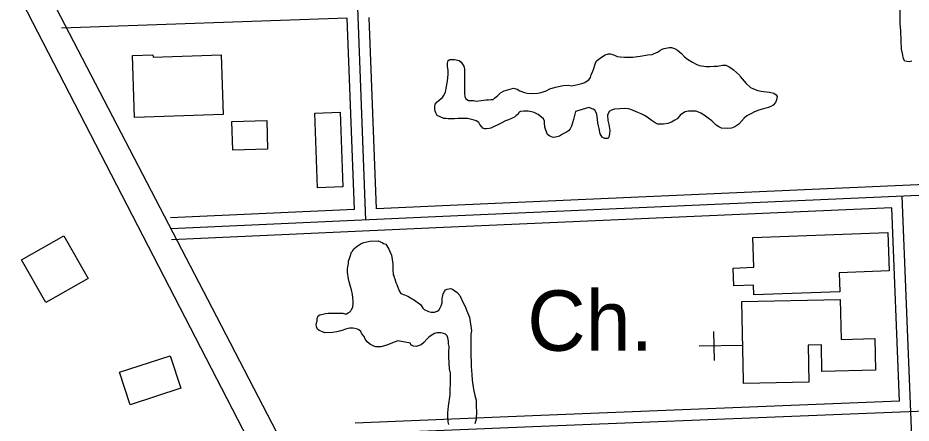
# Model space of a CAD drawing. Extents: x 3313442 to 3351311, y 721974 to 747360.
# Drawn here: x 3328908 to 3330135, y 735140 to 735697 of the extents above; entities that cross this region are included whole.
import ezdxf

# ---------------------------------------------------------------- set-up
doc = ezdxf.new("R2010")
doc.units = 0
for name, color, linetype in [('V-BLDG-OTLN', 7, 'Continuous'), ('V-ROAD-CNTR', 7, 'Continuous'), ('V-SITE-OTLN', 7, 'Continuous'), ('V-SITE-OTLN-IDEN', 7, 'Continuous'), ('V-SITE-VEGE', 7, 'Continuous')]:
    doc.layers.add(name, color=color, linetype=linetype)

msp = doc.modelspace()

# ---------------------------------------------------------------- linework, layer by layer
at = {"layer": 'V-BLDG-OTLN'}
for points in [[(3329067.9, 735559.9), (3329065.1, 735645.1), (3329093.4, 735646), (3329093.5, 735642.7), (3329187.1, 735645.9), (3329189.9, 735564)], [(3329319.6, 735463.2), (3329315.7, 735565.8), (3329350.4, 735567.2), (3329354.3, 735464.5)], [(3329203, 735515.1), (3329201.8, 735554.5), (3329249.7, 735555.9), (3329250.9, 735516.5)], [(3328913, 735364.2), (3328971.1, 735397.3), (3329004.5, 735338.4), (3328946.4, 735305.4)], [(3329917.4, 735394.7), (3330102.7, 735401.6), (3330104.6, 735348.9), (3330035.9, 735346.4), (3330036.9, 735320.3), (3329918.9, 735315.9), (3329918.4, 735329.5), (3329891.3, 735328.5), (3329890.4, 735352.8), (3329918.9, 735353.9)], [(3329904.6, 735198.3), (3329902.3, 735306.9), (3330037.4, 735309.7), (3330038.5, 735254.9), (3330084.9, 735255.9), (3330085.8, 735212.4), (3330012.3, 735210.9), (3330011.5, 735247.3), (3329993.2, 735246.9), (3329994.3, 735195.9), (3329904.7, 735194)], [(3329047.6, 735209.9), (3329117.1, 735232.4), (3329131.6, 735187.6), (3329062.1, 735165.1)]]:
    msp.add_lwpolyline(points, close=True, dxfattribs=at)
at = {"layer": 'V-ROAD-CNTR'}
for points in [[(3329385.8, 735418.9), (3329331.6, 736855.2)], [(3328760.8, 736081.2), (3328936.7, 735756.3), (3329174.1, 735298.9), (3331685.5, 730453.7)], [(3328913.4, 735719.2), (3329483.8, 734613.6), (3331153.1, 731395.2)], [(3329360.3, 735696.3), (3328967.6, 735682.7)], [(3329370.2, 735433.2), (3329360.3, 735696.3)], [(3329400.2, 735434.5), (3329390.3, 735697.3)], [(3332480.2, 735555.8), (3329491.7, 735423.6), (3329118, 735406.9)], [(3330993.8, 735505), (3329491.1, 735438.6), (3329400.2, 735434.5)], [(3330146.4, 734858.1), (3330122.5, 735451.5)], [(3329370.2, 735433.2), (3329117.4, 735421.9)], [(3330108.2, 735435.8), (3329492.4, 735408.6), (3329118.7, 735391.9)], [(3330118.9, 735169.7), (3330108.2, 735435.8)], [(3332772.9, 735263.5), (3332071.4, 735231), (3330946.1, 735187.6), (3329615.1, 735134.6), (3329371.6, 735124.7)], [(3330118.9, 735169.7), (3329614.5, 735149.6), (3329371, 735139.7)]]:
    msp.add_lwpolyline(points, dxfattribs=at)
at = {"layer": 'V-SITE-OTLN'}
for p, q in [((3329863.2, 735265.7), (3329864, 735225.7)), ((3329903.6, 735246.5), (3329843.6, 735245.3))]:
    msp.add_line(p, q, dxfattribs=at)
at = {"layer": 'V-SITE-VEGE'}
for points in [[(3330135.6, 735637.5), (3330132.2, 735636.4), (3330126.3, 735637.4), (3330124.5, 735640.5), (3330122.8, 735647.7), (3330121.7, 735653.6), (3330120.9, 735665.7), (3330120.8, 735678.4), (3330120.1, 735684.3), (3330119.7, 735688.7), (3330119.6, 735700.4), (3330119.9, 735709.1), (3330119.8, 735715.3), (3330120.4, 735724.6), (3330120.4, 735730.1), (3330121, 735736.3), (3330121, 735739.4), (3330122, 735743.2), (3330122.7, 735745.3), (3330127.8, 735750.1), (3330131.9, 735753.6), (3330138.1, 735758.1)], [(3329700.1, 735631.9), (3329701.1, 735634.7), (3329702.8, 735637.8), (3329711, 735643.7), (3329714.4, 735645.8), (3329718.9, 735647.3), (3329721.3, 735647.3), (3329724.4, 735646.3), (3329727.2, 735645.6), (3329731, 735643.6), (3329735.1, 735643.3), (3329741, 735642.6), (3329752.7, 735642.7), (3329758.9, 735643.8), (3329762.7, 735644.2), (3329773, 735646), (3329778.9, 735646.4), (3329780.9, 735647.4), (3329787.1, 735650.2), (3329789.5, 735652), (3329792.9, 735653.7), (3329795.7, 735654.8), (3329802.6, 735655.9), (3329805.7, 735655.9), (3329809.8, 735654.5), (3329814, 735652.2), (3329819.2, 735647.7), (3329823.7, 735643.3), (3329827.5, 735639.9), (3329834.4, 735635.8), (3329839.3, 735633.1)], [(3329638.5, 735534.3), (3329635.4, 735536.7), (3329632.9, 735542.5), (3329631.8, 735546.6), (3329631.4, 735552.5), (3329631.1, 735554.9), (3329630, 735558), (3329622.7, 735563.8), (3329617.2, 735566.5), (3329613.4, 735567.5), (3329608.6, 735568.5), (3329603, 735568.4), (3329598.2, 735568.1), (3329596.2, 735567), (3329594.5, 735563.9), (3329592.4, 735562.5), (3329590, 735560.4), (3329581.8, 735556.6), (3329577.7, 735555.1), (3329571.8, 735552), (3329557.4, 735545.3), (3329555, 735544.6), (3329551.6, 735544.3), (3329549.1, 735544.2), (3329546.7, 735545.2), (3329545.3, 735547), (3329542.2, 735550.4), (3329540.8, 735552.8), (3329537.3, 735555.2), (3329534.6, 735556.2), (3329525.2, 735558.5), (3329512.8, 735558.4), (3329507.7, 735558), (3329498.7, 735558), (3329496, 735558.3), (3329492.9, 735558.3), (3329483.9, 735562.7), (3329481.8, 735566.1), (3329481.1, 735568.5), (3329480.7, 735571.9), (3329480.7, 735574.4), (3329481, 735578.1), (3329483.7, 735581.6), (3329489.2, 735586.1), (3329491.2, 735587.5), (3329492.6, 735589.6), (3329495, 735594.5), (3329496, 735600.3), (3329498, 735609.6), (3329498.3, 735614.8), (3329498.9, 735619), (3329498.9, 735624.5), (3329498.1, 735630.3), (3329497.8, 735634.5), (3329498.8, 735638.2), (3329501.2, 735639.6), (3329507.4, 735639.7), (3329513.9, 735638), (3329516.7, 735636), (3329520.5, 735630.2), (3329521.3, 735626.4), (3329521.5, 735592.6), (3329521.9, 735588.8), (3329523.3, 735585.7), (3329526.8, 735583.3), (3329529.9, 735583), (3329533.7, 735583), (3329537.5, 735582.4), (3329547.4, 735583.5), (3329551.2, 735584.2), (3329554.3, 735584.2), (3329557.4, 735584.6), (3329560.5, 735584.6), (3329562.9, 735586.7), (3329566.7, 735589.5), (3329570.8, 735593.7), (3329575.6, 735596.5), (3329588.7, 735600), (3329593.5, 735599), (3329597.3, 735596.7), (3329603.9, 735594.3), (3329607.3, 735593.3), (3329613.5, 735593), (3329621.8, 735593.1), (3329626.6, 735594.1), (3329633.5, 735596.6), (3329638.3, 735599.1), (3329646.5, 735601.5), (3329656.9, 735604), (3329663.8, 735604.1), (3329668.6, 735603.4), (3329676.8, 735605.2), (3329682.3, 735606.6), (3329686.5, 735608.1), (3329689.9, 735610.2), (3329692, 735611.5), (3329694.3, 735615), (3329695.3, 735618.5), (3329697.7, 735623.7), (3329699.1, 735627.1), (3329700.1, 735631.9)], [(3329839.3, 735633.1), (3329843.8, 735631.4), (3329853.4, 735630.1), (3329857.9, 735630.1), (3329864.1, 735630.2), (3329868.6, 735630.5), (3329875.8, 735631.6), (3329880.3, 735631.7), (3329884.8, 735629.6), (3329887.2, 735628.3), (3329891, 735625.2), (3329899, 735618), (3329900.1, 735616.3), (3329908.4, 735606.4), (3329914.3, 735601.3), (3329918.1, 735599.2), (3329924, 735596.9), (3329928.8, 735595.9), (3329936.1, 735594.9), (3329940.2, 735594.6), (3329946.4, 735593.3), (3329949.2, 735591.2), (3329950.9, 735588.5), (3329949.9, 735584.3), (3329948.6, 735580.5), (3329945.2, 735576.7), (3329942.1, 735575), (3329938.3, 735573.6), (3329925.6, 735569.7), (3329919.4, 735567.5), (3329915.6, 735565.4), (3329909.1, 735562.3), (3329905.3, 735558.8), (3329898.2, 735550.8), (3329892.7, 735547), (3329887.9, 735545.2), (3329882.4, 735544.8), (3329874.1, 735545.1), (3329870.6, 735546.8), (3329866.8, 735549.5), (3329860.9, 735555.4), (3329856.1, 735559.1), (3329850.5, 735563.2), (3329845.7, 735565.6), (3329841.9, 735567.6), (3329839.4, 735568.6), (3329828.8, 735568.5), (3329824.3, 735567.5), (3329820.9, 735565.4), (3329817.4, 735562.9), (3329816.1, 735561.2), (3329813.3, 735558.1), (3329810.3, 735556), (3329805.5, 735553.2), (3329800.6, 735551.8), (3329794.8, 735550.7), (3329786.9, 735550.6), (3329783.1, 735552.7), (3329777.5, 735556.4), (3329772.3, 735560.2), (3329768.5, 735562.5), (3329764, 735564.9), (3329759.5, 735566.9), (3329749.8, 735570.7), (3329746.7, 735571.7), (3329740.5, 735572), (3329734.7, 735571.9), (3329727.4, 735571.2), (3329723.3, 735570.1), (3329720.2, 735568), (3329717.8, 735563.2), (3329718.2, 735555.9), (3329719.7, 735550.4), (3329720.8, 735541.8), (3329720.5, 735537.3), (3329719.5, 735532.8), (3329718.4, 735531.1), (3329714, 735531.1), (3329710.5, 735532.8), (3329707.7, 735537.2), (3329707, 735539.6), (3329706.3, 735544.5), (3329705.2, 735548.6), (3329704.5, 735552.7), (3329704.1, 735557.5), (3329703, 735564.1), (3329702, 735566.5), (3329700.2, 735569.9), (3329698.1, 735571.3), (3329691.9, 735573.6), (3329673.7, 735568), (3329671, 735556.9), (3329668.3, 735547.9), (3329666.6, 735544.1), (3329664.3, 735541.7), (3329661.2, 735539.6), (3329656, 735536.8), (3329651.9, 735534.4), (3329646.1, 735532.6), (3329643, 735532.2), (3329638.5, 735534.3)], [(3329318.7, 735280.5), (3329319, 735283.6), (3329320.3, 735287), (3329322.7, 735288.8), (3329330.6, 735290.6), (3329334.1, 735290.9), (3329347.5, 735291), (3329354.1, 735290.8), (3329356.8, 735290.1), (3329359.2, 735290.1), (3329361.6, 735291.2), (3329363.4, 735292.2), (3329365.1, 735293.9), (3329366.1, 735296), (3329368.1, 735299.1), (3329368.4, 735304), (3329368.4, 735306.7), (3329368, 735312.6), (3329367.3, 735316.4), (3329365.9, 735322.9), (3329364.5, 735327.4), (3329363, 735333.9), (3329362, 735338), (3329360.8, 735347.3), (3329360.8, 735352.2), (3329361.8, 735359.1), (3329362.1, 735362.2), (3329363.8, 735367.3), (3329364.5, 735370.1), (3329366.1, 735374.6), (3329367.5, 735376.3), (3329369.2, 735379.4), (3329373.7, 735382.9), (3329377.8, 735385.7), (3329379.5, 735386.8), (3329382.9, 735388.2), (3329391.2, 735390), (3329402.9, 735390.1), (3329406, 735389), (3329408.4, 735388), (3329410.1, 735386.7), (3329413.3, 735385.7), (3329417.5, 735378.8), (3329421, 735370.6), (3329422.8, 735358.5), (3329422.8, 735350.9), (3329423.2, 735343.7), (3329424.3, 735342), (3329424.7, 735339.9), (3329425.4, 735337.9), (3329426.8, 735333), (3329428.2, 735330.3), (3329431.7, 735321.4), (3329433.8, 735317.9), (3329439, 735316.3), (3329443.5, 735314.2), (3329449.4, 735310.8), (3329451.4, 735309.8), (3329460.8, 735303), (3329462.5, 735299.9), (3329463.9, 735297.8), (3329466, 735295.8), (3329471.9, 735293.1), (3329475.4, 735292.4), (3329478.1, 735292.1), (3329480.2, 735292.1), (3329483.6, 735293.5), (3329486, 735294.9), (3329488.1, 735298), (3329489.4, 735300.8), (3329490.8, 735305)], [(3329490.8, 735305), (3329490.7, 735311.2), (3329491.7, 735315), (3329492, 735317.4), (3329493.7, 735320.8), (3329495.1, 735322.9), (3329497.5, 735324), (3329502, 735325), (3329504.7, 735324), (3329511.3, 735319.2), (3329514.8, 735315.1), (3329520.1, 735304.2), (3329522.5, 735299.3), (3329523.9, 735295.2), (3329528.1, 735285.3), (3329530.7, 735266.7), (3329530, 735262.2), (3329530.2, 735237.4), (3329529.9, 735232.6), (3329530.3, 735223.9), (3329530.4, 735217.4), (3329531.2, 735206.7), (3329531.6, 735198.8), (3329533, 735189.2), (3329533.8, 735186.4), (3329535.5, 735177.5), (3329537.3, 735171.3), (3329537.4, 735162), (3329537.8, 735155.8), (3329537.5, 735145.4), (3329535.5, 735138.9)], [(3329500, 735137.9), (3329499, 735141.3), (3329498.6, 735148.6), (3329498.5, 735153.7), (3329499.1, 735163), (3329501.4, 735178.6), (3329501.4, 735185.1), (3329502, 735194.4), (3329501.9, 735208.6), (3329500.8, 735214.4), (3329499.6, 735230.2), (3329499.6, 735236.8), (3329500.2, 735245.1), (3329499.5, 735248.8), (3329499.1, 735252.3), (3329498.4, 735257.1), (3329497.7, 735259.5), (3329495.2, 735261.9), (3329492.5, 735262.9), (3329488.7, 735263.9), (3329483.5, 735263.9), (3329480.1, 735262.8), (3329475.3, 735260), (3329472.2, 735257.9), (3329470.1, 735255.5), (3329465.3, 735250.6), (3329461.6, 735247.5), (3329454.7, 735245), (3329451.3, 735245.7), (3329447.8, 735247.4), (3329447.1, 735249.5), (3329429.8, 735252.8), (3329422.6, 735250.3), (3329414.4, 735247.1), (3329406.5, 735244.7), (3329399.6, 735244.6), (3329396.8, 735245.6), (3329392.3, 735247.6), (3329390.2, 735249), (3329387.8, 735251.4), (3329385, 735255.2), (3329383.6, 735258.6), (3329380.5, 735262.4), (3329379.1, 735265.5), (3329376, 735267.8), (3329374.2, 735268.9), (3329370.8, 735269.9), (3329367.7, 735270.2), (3329363.9, 735270.2), (3329361.5, 735269.8), (3329357.7, 735268.7), (3329354.6, 735267.7), (3329349.4, 735266.3), (3329346, 735265.2), (3329340.1, 735264.1), (3329329.5, 735264), (3329326.4, 735265.4), (3329321.9, 735267.1), (3329319.4, 735268.8), (3329318, 735272.2), (3329317.7, 735275.6), (3329318.7, 735280.5)]]:
    msp.add_lwpolyline(points, dxfattribs=at)

# ---------------------------------------------------------------- texts
at = {"layer": 'V-SITE-OTLN-IDEN'}
msp.add_text('Ch.', height=83, dxfattribs=at).set_placement((3329607.5, 735239.2))

doc.saveas('drawing.dxf')
